Omron CX-Programmer project myProject (CX-Programmer 9.52)

# PLC PLC1: CP1L M

## Global symbols (name address type ; comment)
100.00 BOOL  ; PID Output
100.01 BOOL  ; PID Output
2 CHANNEL  ; Channel 0 (PV)
4 CHANNEL  ; Channel 2 (PV)
D100 CHANNEL  ; Set Point
D101 CHANNEL  ; Max. Set Point
D102 CHANNEL  ; Min. Set Point
D103 CHANNEL  ; Control Period PID Output
D104 CHANNEL  ; Manual P constant
D105 CHANNEL  ; Manual I constant
D106 CHANNEL  ; Manual D constant
D107 CHANNEL  ; Status Code
D108 CHANNEL  ; User Data Information - P constant
D109 CHANNEL  ; User Data Information - I constant
D110 CHANNEL  ; User Data Information - D constant
D120 CHANNEL  ; 2PID Parameter
D200 CHANNEL  ; Set Point
D201 CHANNEL  ; Max. Set Point
D202 CHANNEL  ; Min. Set Point
D203 CHANNEL  ; Control Period PID Output
D204 CHANNEL  ; Manual P constant
D205 CHANNEL  ; Manual I constant
D206 CHANNEL  ; Manual D constant
D207 CHANNEL  ; Status Code
D208 CHANNEL  ; User Data Information - P constant
D209 CHANNEL  ; User Data Information - I constant
D210 CHANNEL  ; User Data Information - D constant
D220 CHANNEL  ; 2PID Parameter
W0.00 BOOL  ; Enable PID Function Block
W0.01 BOOL  ; Start Auto-Tuning
W0.02 BOOL  ; Stop Auto-Tuning
W0.03 BOOL  ; Write PID constants
W0.04 BOOL  ; Reset Error
W0.05 BOOL  ; Auto Tuning Status
W0.06 BOOL  ; Error Bit
W1.00 BOOL  ; Enable PID Function
W1.01 BOOL  ; Start Auto-Tuning
W1.02 BOOL  ; Stop Auto-Tuning
W1.03 BOOL  ; Write PID constants
W1.04 BOOL  ; Reset Error
W1.05 BOOL  ; Auto Tuning Status
W1.06 BOOL  ; Error Bit
W200.00 BOOL  ; Enable PID
CP1W_TS003_Input0 TC_2PID_function_block
CP1W_TS003_Input2 TC_2PID_function_block

## Program Program1 (cyclic task 0)
Local symbols
P_ON BOOL

### Section Section1

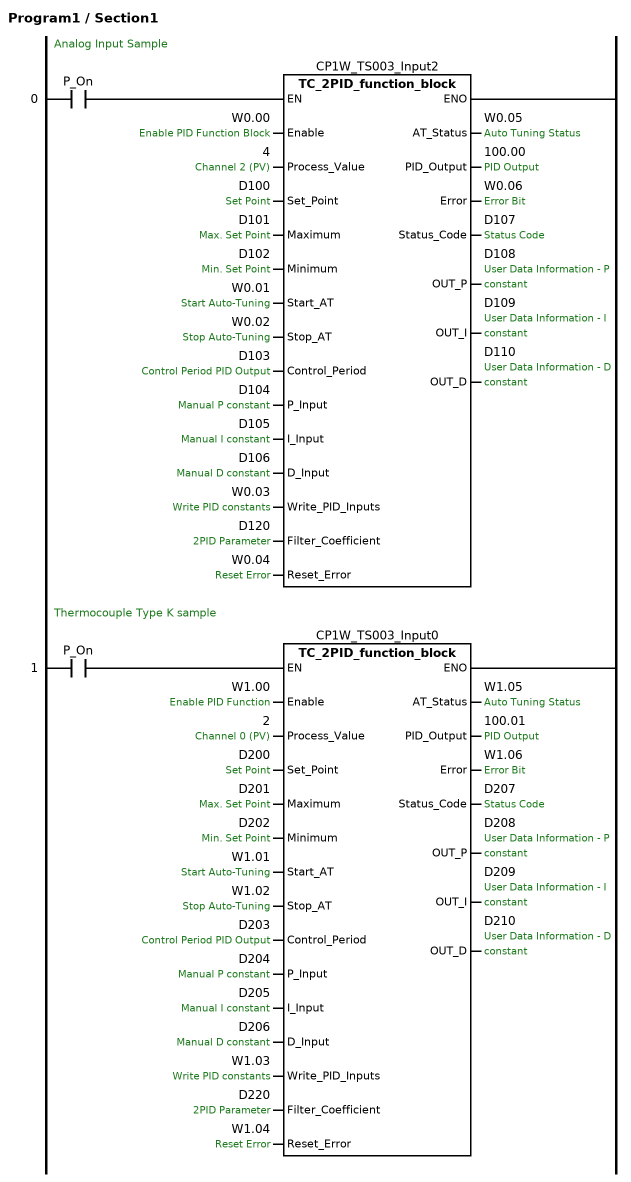
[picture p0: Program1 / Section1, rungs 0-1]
; rung 0: Analog Input Sample
LD P_On
CALL CP1W_TS003_Input2 : TC_2PID_function_block (Enable := W0.00, Process_Value := 4, Set_Point := D100, Maximum := D101, Minimum := D102, Start_AT := W0.01, Stop_AT := W0.02, Control_Period := D103, P_Input := D104, I_Input := D105, D_Input := D106, Write_PID_Inputs := W0.03, Filter_Coefficient := D120, Reset_Error := W0.04, AT_Status => W0.05, PID_Output => 100.00, Error => W0.06, Status_Code => D107, OUT_P => D108, OUT_I => D109, OUT_D => D110)  ; Enable PID Function Block, Channel 2 (PV), Set Point, Max. Set Point, Min. Set Point, Start Auto-Tuning, Stop Auto-Tuning, Control Period PID Output, Manual P constant, Manual I constant, Manual D constant, Write PID constants, 2PID Parameter, Reset Error, Auto Tuning Status, PID Output, Error Bit, Status Code, User Data Information - P constant, User Data Information - I constant, User Data Information - D constant
; rung 1: Thermocouple Type K sample
LD P_On
CALL CP1W_TS003_Input0 : TC_2PID_function_block (Enable := W1.00, Process_Value := 2, Set_Point := D200, Maximum := D201, Minimum := D202, Start_AT := W1.01, Stop_AT := W1.02, Control_Period := D203, P_Input := D204, I_Input := D205, D_Input := D206, Write_PID_Inputs := W1.03, Filter_Coefficient := D220, Reset_Error := W1.04, AT_Status => W1.05, PID_Output => 100.01, Error => W1.06, Status_Code => D207, OUT_P => D208, OUT_I => D209, OUT_D => D210)  ; Enable PID Function, Channel 0 (PV), Set Point, Max. Set Point, Min. Set Point, Start Auto-Tuning, Stop Auto-Tuning, Control Period PID Output, Manual P constant, Manual I constant, Manual D constant, Write PID constants, 2PID Parameter, Reset Error, Auto Tuning Status, PID Output, Error Bit, Status Code, User Data Information - P constant, User Data Information - I constant, User Data Information - D constant

### Section END
; rung 0
END(001)

## Function block TC_2PID_function_block
VAR_INPUT
  Enable : BOOL;
  Process_Value : INT;
  Set_Point : INT;
  Maximum : INT;  (* Maximum set value *)
  Minimum : INT;  (* Minimum set value *)
  Start_AT : BOOL;
  Stop_AT : BOOL;
  Control_Period : WORD;  (* output control period *)
  P_Input : INT;
  I_Input : INT;
  D_Input : INT;
  Write_PID_Inputs : BOOL;  (* Adjust PID Parameters manually. *)
  Filter_Coefficient : WORD;
  Reset_Error : BOOL;
END_VAR
VAR_OUTPUT
  AT_Status : BOOL;
  PID_Output : BOOL;
  Error : BOOL;
  Status_Code : INT;  (* Display Status or Error Code *)
  OUT_P : WORD;
  OUT_I : WORD;
  OUT_D : WORD;
END_VAR
VAR
  C : ARRAY[0..4] OF WORD;
  PIDSV : WORD;
  PIDPV : WORD;
  PIDC : ARRAY[0..40] OF WORD;
  PIDMV : UINT;
  TPOC : ARRAY[0..6] OF WORD;
  RETAIN mOUT_P : INT;
  RETAIN mOUT_I : INT;
  RETAIN mOUT_D : INT;
  mOUT_Restore : BOOL;
END_VAR

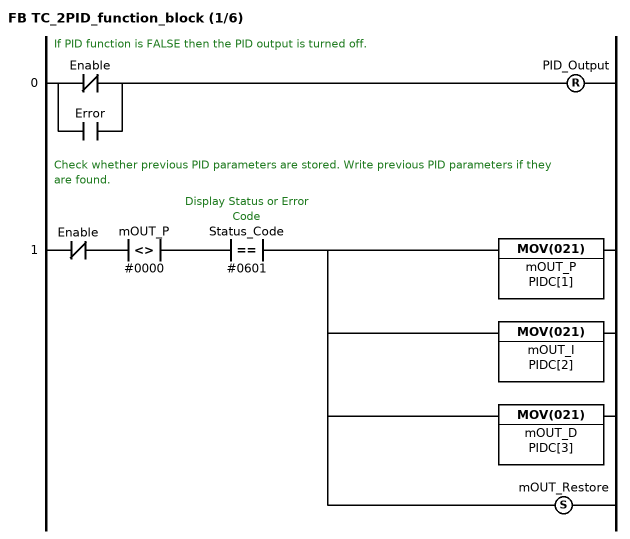
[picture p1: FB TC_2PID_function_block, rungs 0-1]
; rung 0: If PID function is FALSE then the PID output is turned off.
LDNOT Enable
OR Error
RSET PID_Output
; rung 1: Check whether previous PID parameters are stored. Write previous PID parameters if they are found.
LDNOT Enable
AND<>(305) mOUT_P #0000
AND=(300) Status_Code #0601  ; Display Status or Error Code
MOV(021) mOUT_P PIDC[1]
MOV(021) mOUT_I PIDC[2]
MOV(021) mOUT_D PIDC[3]
SET mOUT_Restore

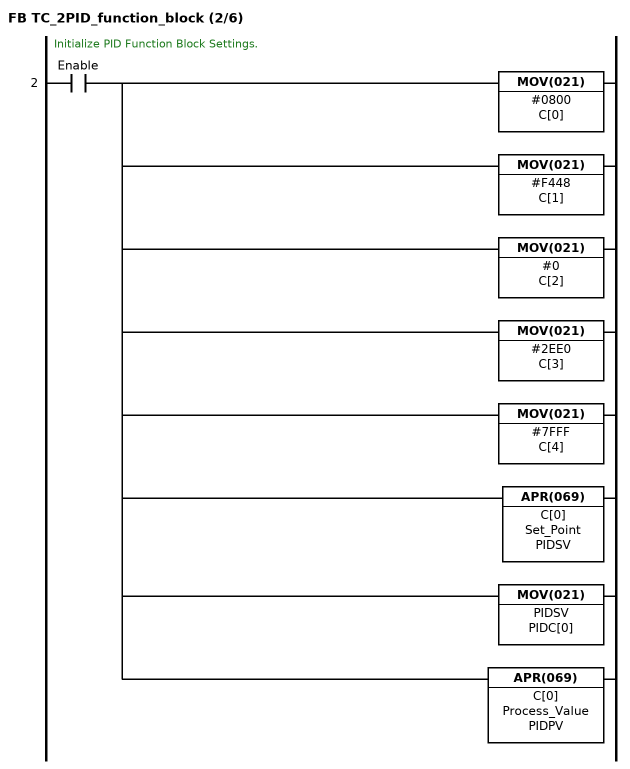
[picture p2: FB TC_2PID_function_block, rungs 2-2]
; rung 2: Initialize PID Function Block Settings.
LD Enable
MOV(021) #0800 C[0]
MOV(021) #F448 C[1]
MOV(021) #0 C[2]
MOV(021) #2EE0 C[3]
MOV(021) #7FFF C[4]
APR(069) C[0] Set_Point PIDSV
MOV(021) PIDSV PIDC[0]
APR(069) C[0] Process_Value PIDPV

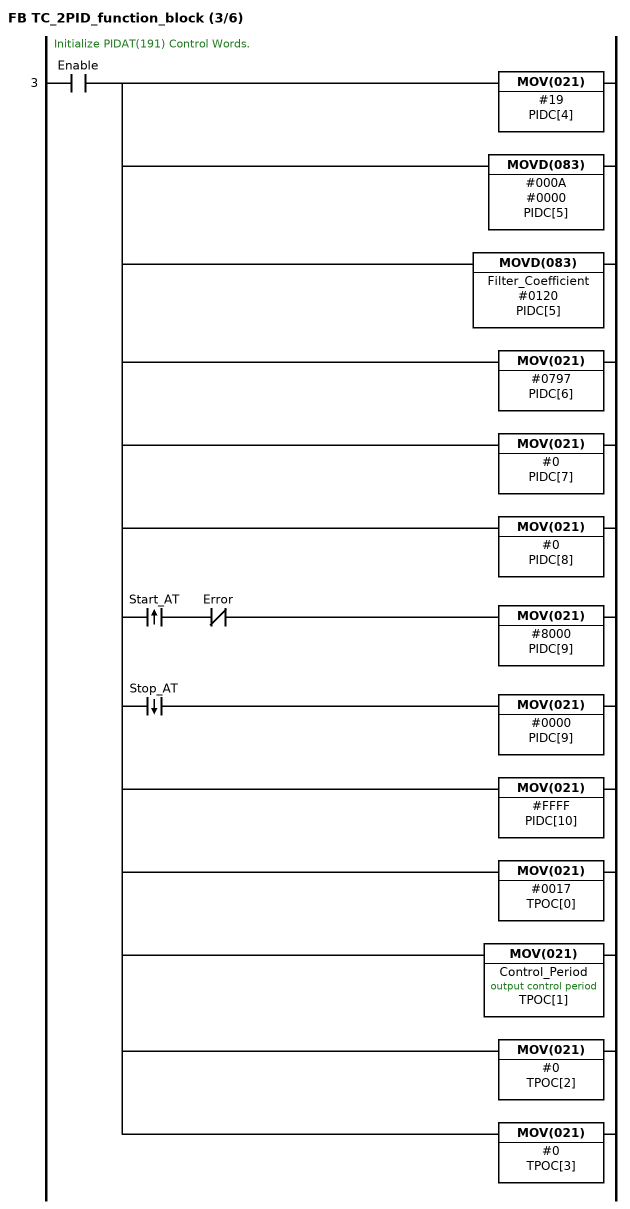
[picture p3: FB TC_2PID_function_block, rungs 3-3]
; rung 3: Initialize PIDAT(191) Control Words.
LD Enable
OUT TR0
MOV(021) #19 PIDC[4]
MOVD(083) #000A #0000 PIDC[5]
MOVD(083) Filter_Coefficient #0120 PIDC[5]
MOV(021) #0797 PIDC[6]
MOV(021) #0 PIDC[7]
MOV(021) #0 PIDC[8]
@AND Start_AT
ANDNOT Error
MOV(021) #8000 PIDC[9]
LD TR0
%AND Stop_AT
MOV(021) #0000 PIDC[9]
LD TR0
MOV(021) #FFFF PIDC[10]
MOV(021) #0017 TPOC[0]
MOV(021) Control_Period TPOC[1]  ; output control period
MOV(021) #0 TPOC[2]
MOV(021) #0 TPOC[3]

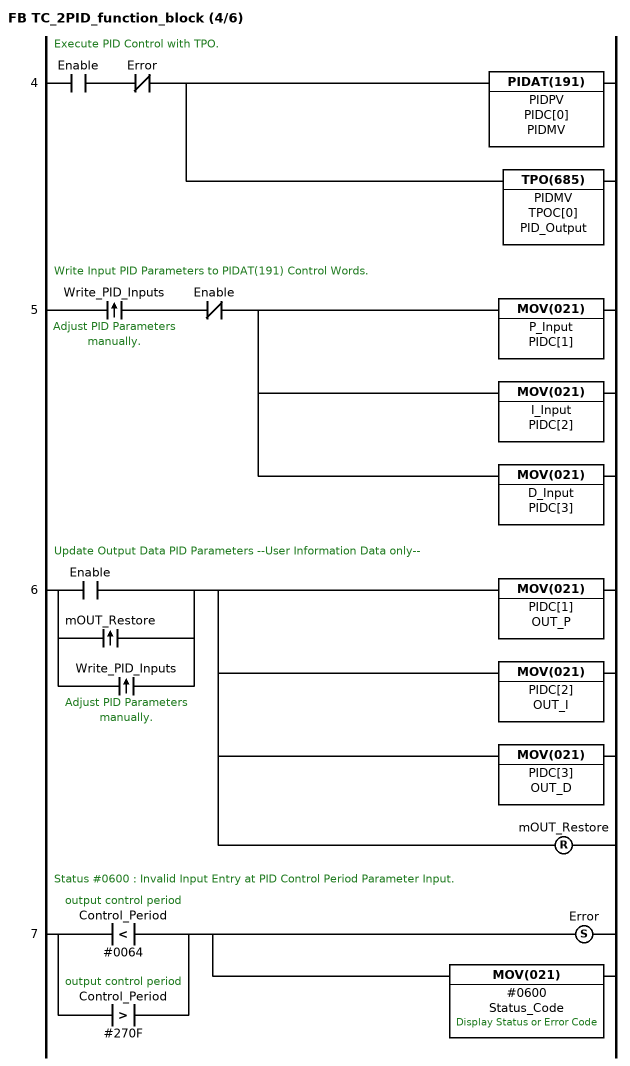
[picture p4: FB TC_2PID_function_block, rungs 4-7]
; rung 4: Execute PID Control with TPO.
LD Enable
ANDNOT Error
PIDAT(191) PIDPV PIDC[0] PIDMV
TPO(685) PIDMV TPOC[0] PID_Output
; rung 5: Write Input PID Parameters to PIDAT(191) Control Words.
@LD Write_PID_Inputs  ; Adjust PID Parameters manually.
ANDNOT Enable
MOV(021) P_Input PIDC[1]
MOV(021) I_Input PIDC[2]
MOV(021) D_Input PIDC[3]
; rung 6: Update Output Data PID Parameters --User Information Data only--
LD Enable
@OR mOUT_Restore
@OR Write_PID_Inputs  ; Adjust PID Parameters manually.
MOV(021) PIDC[1] OUT_P
MOV(021) PIDC[2] OUT_I
MOV(021) PIDC[3] OUT_D
RSET mOUT_Restore
; rung 7: Status #0600 : Invalid Input Entry at PID Control Period Parameter Input.
LD<(310) Control_Period #0064  ; output control period
OR>(320) Control_Period #270F  ; output control period
SET Error
MOV(021) #0600 Status_Code  ; Display Status or Error Code

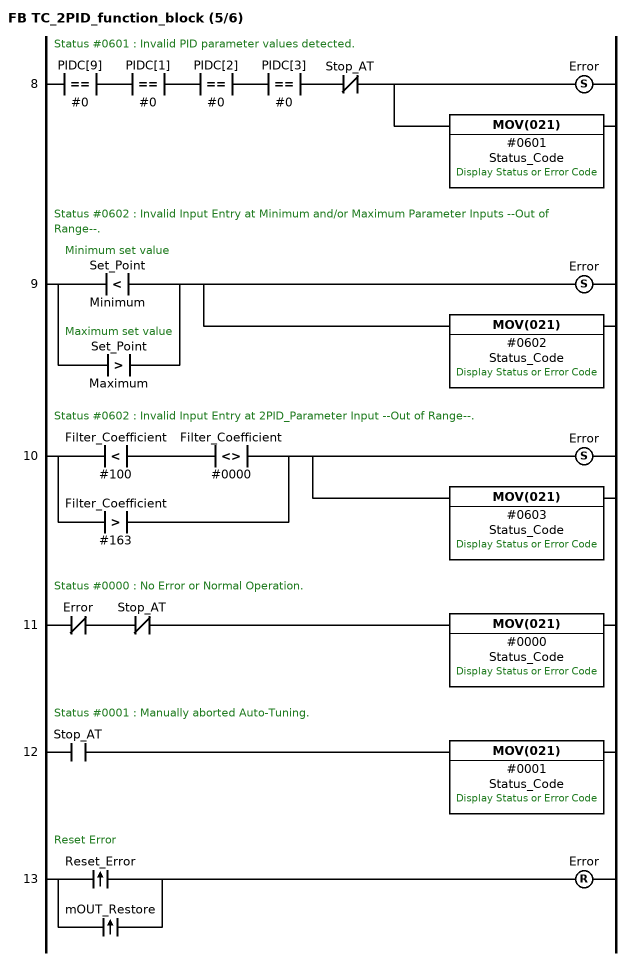
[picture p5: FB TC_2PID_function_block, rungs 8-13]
; rung 8: Status #0601 : Invalid PID parameter values detected.
LD=(300) PIDC[9] #0
AND=(300) PIDC[1] #0
AND=(300) PIDC[2] #0
AND=(300) PIDC[3] #0
ANDNOT Stop_AT
SET Error
MOV(021) #0601 Status_Code  ; Display Status or Error Code
; rung 9: Status #0602 : Invalid Input Entry at Minimum and/or Maximum Parameter Inputs --Out of Range--.
LD<S(312) Set_Point Minimum  ; Minimum set value
OR>S(322) Set_Point Maximum  ; Maximum set value
SET Error
MOV(021) #0602 Status_Code  ; Display Status or Error Code
; rung 10: Status #0602 : Invalid Input Entry at 2PID_Parameter Input --Out of Range--.
LD<S(312) Filter_Coefficient #100
AND<>(305) Filter_Coefficient #0000
OR>S(322) Filter_Coefficient #163
SET Error
MOV(021) #0603 Status_Code  ; Display Status or Error Code
; rung 11: Status #0000 : No Error or Normal Operation.
LDNOT Error
ANDNOT Stop_AT
MOV(021) #0000 Status_Code  ; Display Status or Error Code
; rung 12: Status #0001 : Manually aborted Auto-Tuning.
LD Stop_AT
MOV(021) #0001 Status_Code  ; Display Status or Error Code
; rung 13: Reset Error
@LD Reset_Error
@OR mOUT_Restore
RSET Error

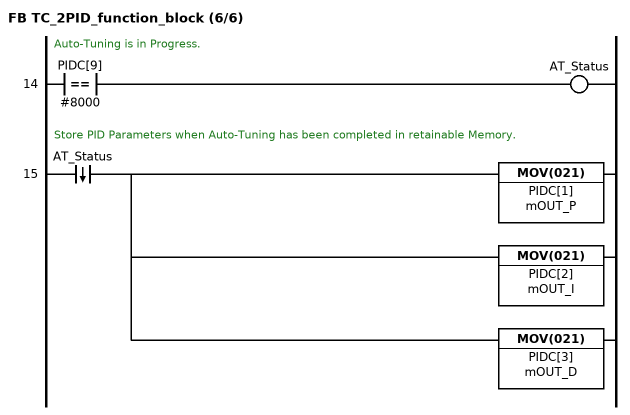
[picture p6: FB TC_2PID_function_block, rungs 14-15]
; rung 14: Auto-Tuning is in Progress.
LD=(300) PIDC[9] #8000
OUT AT_Status
; rung 15: Store PID Parameters when Auto-Tuning has been completed in retainable Memory.
%LD AT_Status
MOV(021) PIDC[1] mOUT_P
MOV(021) PIDC[2] mOUT_I
MOV(021) PIDC[3] mOUT_D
